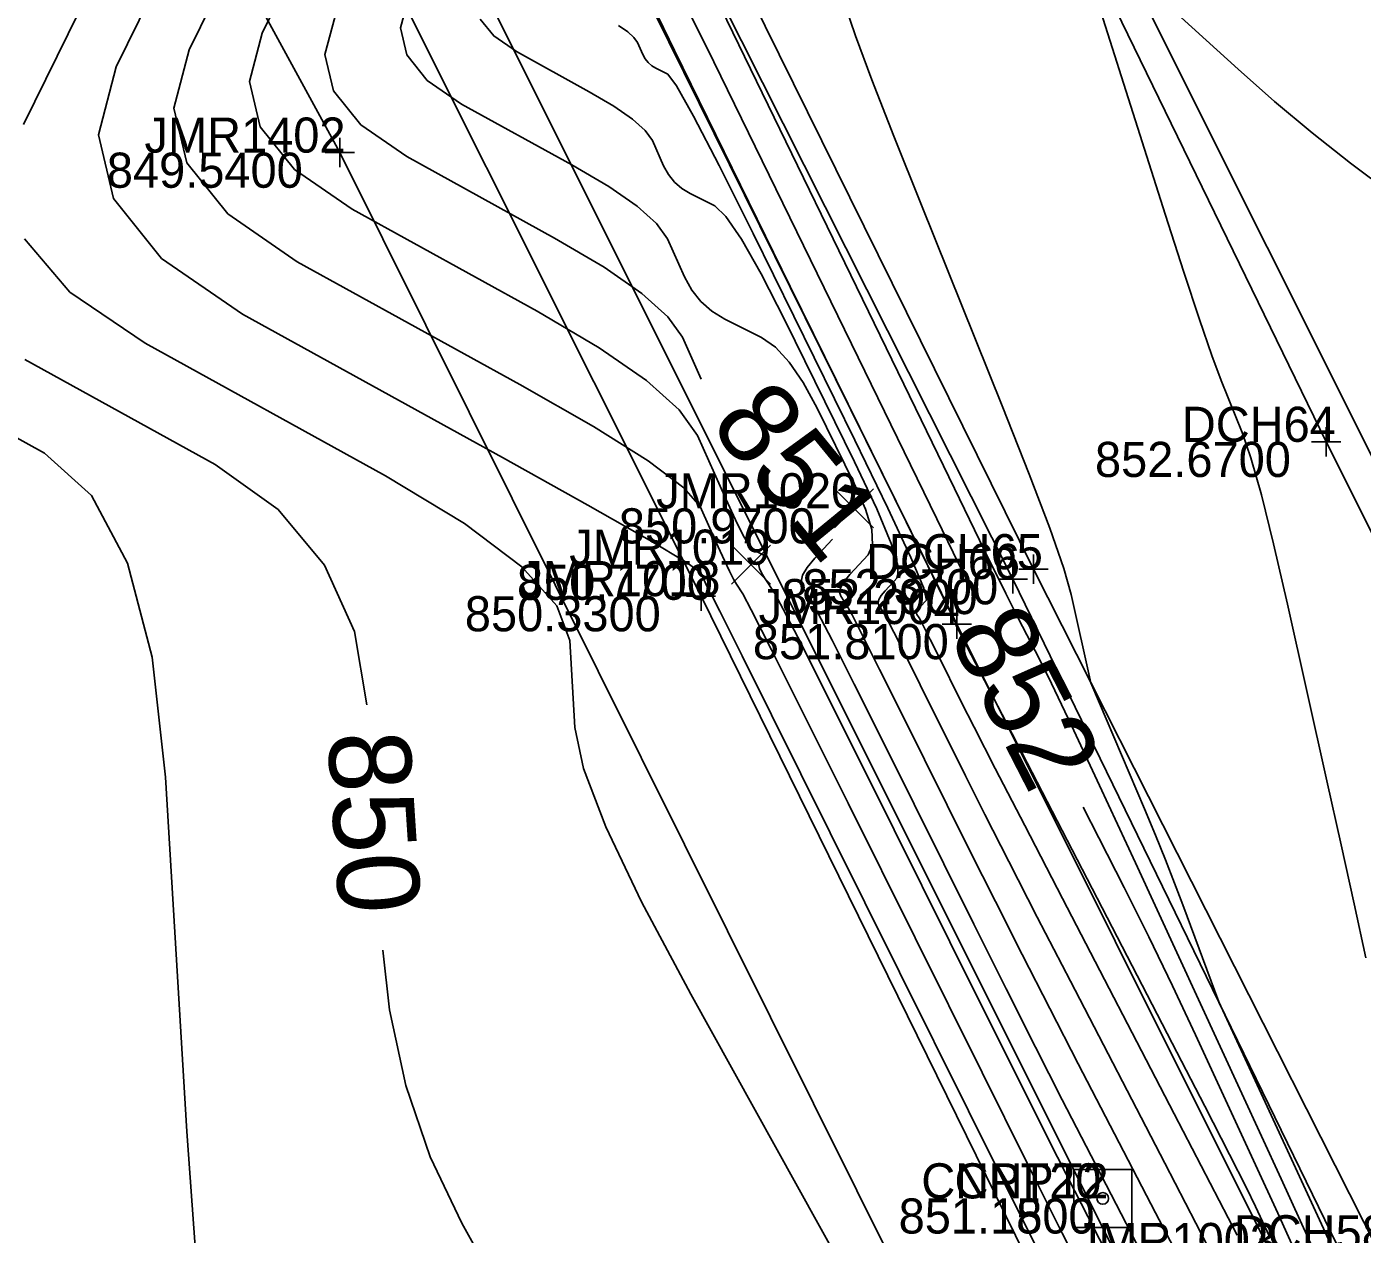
# Model space of a CAD drawing. Extents: x 1654928 to 1810050, y 486881 to 626330.
# Drawn here: x 1801345.62 to 1801391.24, y 489876.6 to 489917.85 of the extents above; entities that cross this region are included whole.
import ezdxf

# ---------------------------------------------------------------- set-up
doc = ezdxf.new("R2010")
doc.units = 0
for name, color, linetype in [('DT_X_Contour_Major', 7, 'Continuous'), ('DT_X_Contour_Minor', 7, 'Continuous'), ('PV_X_EOP', 7, 'Continuous'), ('PV_X_Shoulder', 7, 'Continuous'), ('RD_X_Fence', 7, 'Continuous'), ('RW_X_Esmt_SH', 7, 'Continuous'), ('SV_P_Control_Cells_Set', 7, 'Continuous'), ('SV_X_Break_Lines', 7, 'Continuous'), ('SV_X_Center_of_Pavt', 7, 'Continuous'), ('SV_X_CL_Survey_20', 7, 'Continuous'), ('SV_X_Control_Cells_Found', 7, 'Continuous'), ('SV_X_Occupation_Line', 7, 'Continuous'), ('SV_X_Random_Point', 7, 'Continuous'), ('SV_X_Shot_Marker', 7, 'Continuous'), ('SV_X_Text_Elevation', 7, 'Continuous'), ('SV_X_Text_Name', 7, 'Continuous')]:
    doc.layers.add(name, color=color, linetype=linetype)

msp = doc.modelspace()

# ---------------------------------------------------------------- linework, layer by layer
at = {"layer": 'DT_X_Contour_Major'}
for points in [[(1801344.553, 489964.664), (1801350.197, 489953.606), (1801351.808, 489950.439), (1801352.274, 489949.518), (1801354.342, 489945.414), (1801359.53, 489935.147), (1801360.682, 489932.876), (1801361.734, 489930.824), (1801362.685, 489928.991), (1801363.535, 489927.377), (1801365.669, 489923.365), (1801366.482, 489921.817), (1801367.323, 489920.181), (1801368.19, 489918.458), (1801369.084, 489916.647), (1801372.39, 489909.892), (1801374.021, 489906.547), (1801376.699, 489901.037), (1801377.442, 489899.52), (1801377.866, 489898.669)], [(1801356.15, 489918.213), (1801355.804, 489916.896), (1801356.096, 489915.656), (1801357.029, 489914.495), (1801358.601, 489913.412), (1801363.646, 489910.629), (1801365.338, 489909.635), (1801366.629, 489908.739), (1801367.521, 489907.942), (1801368.012, 489907.244), (1801368.654, 489905.814)], [(1801345.549, 489906.479), (1801352.05, 489902.893), (1801354.204, 489901.363), (1801355.79, 489899.462), (1801356.809, 489897.192), (1801357.237, 489894.691)], [(1801373.141, 489900.342), (1801372.537, 489899.696), (1801372.276, 489899.383), (1801372.12, 489899.114), (1801372.068, 489898.889), (1801372.12, 489898.708), (1801372.398, 489898.285), (1801372.633, 489897.858), (1801373.129, 489896.893), (1801373.886, 489895.391), (1801374.904, 489893.351), (1801377.967, 489887.196), (1801379.069, 489884.99), (1801380.076, 489882.991), (1801380.988, 489881.197), (1801381.806, 489879.609), (1801383.86, 489875.648)], [(1801381.698, 489891.194), (1801382.241, 489890.146), (1801383.105, 489888.454), (1801383.943, 489886.769), (1801384.753, 489885.091), (1801385.537, 489883.419), (1801387.592, 489878.971), (1801388.351, 489877.322), (1801389.084, 489875.712)], [(1801357.786, 489886.311), (1801358.009, 489884.27), (1801358.57, 489881.682), (1801359.394, 489879.254), (1801360.479, 489876.984), (1801363.724, 489871.142)]]:
    msp.add_lwpolyline(points, dxfattribs=at)
at = {"layer": 'DT_X_Contour_Minor'}
for points in [[(1801343.748, 489949.023), (1801345.654, 489944.672), (1801346.311, 489942.99), (1801346.853, 489941.21), (1801347.28, 489939.331), (1801347.592, 489937.353), (1801348.27, 489931.946), (1801348.519, 489930.099), (1801348.757, 489928.615), (1801348.984, 489927.493), (1801349.2, 489926.733), (1801349.76, 489925.189), (1801349.818, 489924.427), (1801349.574, 489923.3), (1801349.027, 489921.809), (1801348.177, 489919.952), (1801345.505, 489914.513)], [(1801351.803, 489922.842), (1801348.676, 489916.476), (1801348.066, 489914.157), (1801348.582, 489911.976), (1801350.222, 489909.933), (1801352.988, 489908.028), (1801361.865, 489903.132), (1801364.785, 489901.508), (1801366.887, 489900.31), (1801368.173, 489899.539), (1801368.641, 489899.192), (1801368.856, 489898.716), (1801368.901, 489898.621), (1801368.937, 489898.551), (1801368.963, 489898.505), (1801369.02, 489898.419), (1801369.289, 489897.888), (1801370.052, 489896.361), (1801373.062, 489890.318), (1801380.158, 489876.06)], [(1801353.845, 489922.505), (1801351.168, 489917.055), (1801350.645, 489915.07), (1801351.086, 489913.203), (1801352.491, 489911.454), (1801354.859, 489909.823), (1801362.458, 489905.631), (1801364.981, 489904.191), (1801366.848, 489903.016), (1801368.061, 489902.105), (1801368.619, 489901.458), (1801369.235, 489900.087), (1801369.447, 489899.622), (1801369.622, 489899.254), (1801369.76, 489898.983), (1801369.86, 489898.809), (1801370.08, 489898.476), (1801370.366, 489897.935), (1801371.061, 489896.564), (1801372.164, 489894.362), (1801373.676, 489891.329), (1801378.252, 489882.134), (1801379.795, 489879.037), (1801380.991, 489876.643), (1801381.841, 489874.952)], [(1801355.886, 489922.168), (1801353.659, 489917.634), (1801353.224, 489915.983), (1801353.591, 489914.43), (1801354.76, 489912.975), (1801356.73, 489911.618), (1801363.052, 489908.13), (1801365.172, 489906.884), (1801366.791, 489905.762), (1801367.908, 489904.763), (1801368.524, 489903.888), (1801369.497, 489901.719), (1801369.828, 489901.001), (1801370.093, 489900.475), (1801370.292, 489900.139), (1801370.424, 489899.994), (1801370.686, 489899.862), (1801370.766, 489899.812), (1801370.809, 489899.762), (1801370.816, 489899.711), (1801370.785, 489899.659), (1801370.655, 489899.52), (1801370.629, 489899.45), (1801370.647, 489899.343), (1801370.71, 489899.2), (1801370.818, 489899.02), (1801371.165, 489898.492), (1801371.458, 489897.96), (1801372.076, 489896.757), (1801373.02, 489894.883), (1801374.29, 489892.34), (1801378.11, 489884.665), (1801379.432, 489882.014), (1801380.534, 489879.817), (1801381.415, 489878.074), (1801382.075, 489876.786), (1801384.027, 489873.021)], [(1801392.192, 489912.176), (1801390.839, 489913.186), (1801389.522, 489914.225), (1801388.242, 489915.294), (1801386.998, 489916.394), (1801381.278, 489921.594), (1801384.501, 489911.447), (1801385.139, 489909.461), (1801385.672, 489907.852), (1801386.098, 489906.62), (1801386.42, 489905.765), (1801387.135, 489903.988), (1801387.433, 489903.122), (1801387.791, 489901.856), (1801388.207, 489900.191), (1801388.683, 489898.127), (1801390.03, 489892.09), (1801390.515, 489889.909), (1801390.958, 489887.895), (1801391.359, 489886.047)], [(1801369.129, 489918.901), (1801375.971, 489904.816), (1801377.305, 489902.073), (1801378.336, 489899.963), (1801379.063, 489898.487), (1801379.487, 489897.645), (1801380.213, 489896.242), (1801380.622, 489895.413), (1801381.304, 489893.977), (1801382.258, 489891.935), (1801383.485, 489889.287), (1801387.121, 489881.416), (1801388.462, 489878.499), (1801389.76, 489875.65)], [(1801358.642, 489918.793), (1801358.383, 489917.808), (1801358.601, 489916.883), (1801359.298, 489916.016), (1801360.472, 489915.207), (1801364.24, 489913.129), (1801365.503, 489912.386), (1801366.468, 489911.717), (1801367.133, 489911.122), (1801367.5, 489910.6), (1801368.08, 489909.308), (1801368.33, 489908.854), (1801368.643, 489908.462), (1801369.019, 489908.132), (1801369.459, 489907.864), (1801370.718, 489907.232), (1801371.191, 489906.904), (1801371.664, 489906.393), (1801372.139, 489905.701), (1801372.614, 489904.826), (1801373.884, 489902.25), (1801374.271, 489901.373), (1801374.48, 489900.675), (1801374.511, 489900.155), (1801374.364, 489899.813), (1801373.736, 489899.14), (1801373.539, 489898.905), (1801373.421, 489898.702), (1801373.382, 489898.533), (1801373.421, 489898.397), (1801373.631, 489898.078), (1801373.808, 489897.756), (1801374.181, 489897.03), (1801374.751, 489895.898), (1801375.518, 489894.362), (1801377.825, 489889.727), (1801378.706, 489887.967), (1801379.618, 489886.164), (1801380.562, 489884.319), (1801381.536, 489882.431), (1801384.178, 489877.338), (1801385.046, 489875.663)], [(1801366.999, 489918.559), (1801367.744, 489917.038), (1801371.691, 489908.974), (1801375.651, 489900.938), (1801376.394, 489899.43), (1801376.923, 489898.353), (1801377.238, 489897.704), (1801377.341, 489897.485), (1801377.331, 489897.474), (1801377.328, 489897.47), (1801377.326, 489897.467), (1801377.325, 489897.464), (1801377.326, 489897.462), (1801377.329, 489897.457), (1801377.332, 489897.452), (1801377.338, 489897.44), (1801377.347, 489897.421), (1801377.36, 489897.396), (1801377.398, 489897.32), (1801377.439, 489897.24), (1801377.532, 489897.059), (1801377.679, 489896.775), (1801377.879, 489896.39), (1801378.936, 489894.353), (1801384.745, 489883.131), (1801385.856, 489880.979), (1801386.701, 489879.332), (1801387.279, 489878.19), (1801387.59, 489877.552), (1801388.064, 489876.525)], [(1801373.559, 489918.61), (1801373.927, 489917.536), (1801374.487, 489916.035), (1801375.236, 489914.106), (1801376.176, 489911.749), (1801378.937, 489904.895), (1801379.861, 489902.566), (1801380.562, 489900.717), (1801381.04, 489899.348), (1801381.296, 489898.461), (1801381.97, 489895.442), (1801383.798, 489891.132), (1801384.173, 489890.234), (1801384.517, 489889.39), (1801384.828, 489888.599), (1801385.107, 489887.861), (1801386.335, 489884.541), (1801389.294, 489878.136), (1801389.908, 489876.801), (1801390.484, 489875.538)], [(1801361.106, 489918.109), (1801361.567, 489917.536), (1801362.343, 489917.002), (1801364.833, 489915.628), (1801365.668, 489915.137), (1801366.306, 489914.695), (1801366.746, 489914.301), (1801366.989, 489913.957), (1801367.372, 489913.102), (1801367.537, 489912.802), (1801367.744, 489912.543), (1801367.993, 489912.325), (1801368.284, 489912.148), (1801369.116, 489911.73), (1801369.5, 489911.367), (1801370.029, 489910.592), (1801370.702, 489909.404), (1801371.52, 489907.805), (1801373.893, 489902.988), (1801374.652, 489901.387), (1801375.149, 489900.195), (1801375.384, 489899.411), (1801375.357, 489899.037), (1801374.934, 489898.585), (1801374.802, 489898.427), (1801374.723, 489898.291), (1801374.696, 489898.177), (1801374.723, 489898.085), (1801374.863, 489897.871), (1801374.982, 489897.655), (1801375.233, 489897.166), (1801375.617, 489896.406), (1801376.132, 489895.374), (1801377.683, 489892.258), (1801378.343, 489890.944), (1801379.16, 489889.338), (1801380.135, 489887.441), (1801381.267, 489885.253), (1801384.496, 489879.029), (1801385.556, 489876.984), (1801386.774, 489874.627)], [(1801365.834, 489917.888), (1801366.145, 489917.672), (1801366.359, 489917.481), (1801366.477, 489917.313), (1801366.664, 489916.897), (1801366.744, 489916.751), (1801366.845, 489916.624), (1801366.966, 489916.518), (1801367.108, 489916.432), (1801367.513, 489916.228), (1801367.809, 489915.831), (1801368.393, 489914.791), (1801369.265, 489913.108), (1801370.426, 489910.783), (1801373.903, 489903.727), (1801375.034, 489901.401), (1801375.819, 489899.715), (1801376.257, 489898.668), (1801376.349, 489898.261), (1801376.132, 489898.03), (1801376.065, 489897.949), (1801376.024, 489897.879), (1801376.011, 489897.821), (1801376.024, 489897.774), (1801376.096, 489897.664), (1801376.157, 489897.553), (1801376.286, 489897.303), (1801376.482, 489896.914), (1801376.746, 489896.385), (1801377.54, 489894.789), (1801377.98, 489893.92), (1801378.702, 489892.512), (1801379.708, 489890.564), (1801380.998, 489888.075), (1801384.813, 489880.719), (1801386.961, 489876.577)], [(1801345.543, 489910.605), (1801347.091, 489908.778), (1801349.661, 489907.037), (1801357.872, 489902.507), (1801360.575, 489900.882), (1801362.524, 489899.403), (1801363.72, 489898.07), (1801364.163, 489896.883), (1801364.34, 489893.915), (1801364.637, 489892.511), (1801365.395, 489890.524), (1801366.615, 489887.955), (1801368.296, 489884.804), (1801373.394, 489875.625)], [(1801341.437, 489905.92), (1801346.227, 489903.278), (1801347.832, 489901.843), (1801349.056, 489899.522), (1801349.899, 489896.314), (1801350.36, 489892.219), (1801351.08, 489880.117), (1801351.381, 489876.029)]]:
    msp.add_lwpolyline(points, dxfattribs=at)
at = {"layer": 'PV_X_EOP'}
msp.add_lwpolyline([(1801513.785, 489634.043), (1801503.26, 489654.965), (1801492.692, 489675.84), (1801481.803, 489697.704), (1801472.078, 489717.629), (1801460.782, 489739.414), (1801448.005, 489764.97), (1801436.553, 489786.89), (1801425.237, 489809.697), (1801414.345, 489830.894), (1801402.21, 489854.742), (1801391.781, 489876.056), (1801380.008, 489899.32), (1801369.395, 489920.807), (1801356.62, 489946.308), (1801346.845, 489965.404), (1801335.257, 489988.444)], dxfattribs=at)
at = {"layer": 'PV_X_Shoulder'}
msp.add_lwpolyline([(1801513.053, 489633.484), (1801502.425, 489654.401), (1801492.155, 489675.438), (1801481.048, 489697.245), (1801471.095, 489717.056), (1801459.974, 489738.844), (1801446.996, 489764.517), (1801435.938, 489786.184), (1801424.33, 489809.156), (1801413.386, 489830.353), (1801401.606, 489854.259), (1801390.811, 489875.349), (1801379.301, 489898.985), (1801368.607, 489920.204), (1801355.561, 489945.921), (1801346.174, 489964.922), (1801334.144, 489988.199)], dxfattribs=at)
at = {"layer": 'RD_X_Fence'}
msp.add_lwpolyline([(1801327.157, 489980.825), (1801341.337, 489952.815), (1801353.978, 489927.719), (1801368.649, 489898.399), (1801382.749, 489869.731), (1801399.284, 489836.538), (1801405.615, 489823.327), (1801393.757, 489823.044), (1801375.98, 489823.449), (1801361.092, 489823.97), (1801335.059, 489824.221), (1801306.244, 489824.992)], dxfattribs=at)
at = {"layer": 'RW_X_Esmt_SH'}
msp.add_line((1801533.563, 489574.54), (1801308.538, 490024.454), dxfattribs=at)
at = {"layer": 'SV_P_Control_Cells_Set'}
msp.add_lwpolyline([(1801381.382, 489878.82), (1801383.362, 489878.82), (1801383.362, 489876.839), (1801381.382, 489876.839), (1801381.382, 489878.82)], dxfattribs=at)
msp.add_circle((1801382.372, 489877.829), 0.2, dxfattribs=at)
at = {"layer": 'SV_X_Break_Lines'}
msp.add_lwpolyline([(1801419.479, 489816.264), (1801413.606, 489827.582), (1801399.229, 489854.903), (1801388.205, 489875.792), (1801377.391, 489897.446), (1801365.991, 489920.501), (1801353.319, 489946.375), (1801342.526, 489967.898), (1801332.595, 489987.823)], dxfattribs=at)
at = {"layer": 'SV_X_Center_of_Pavt'}
msp.add_lwpolyline([(1801523.585, 489638.313), (1801512.853, 489659.481), (1801502.374, 489680.412), (1801490.819, 489703.952), (1801481.428, 489721.68), (1801470.803, 489742.834), (1801457.335, 489769.613), (1801446.389, 489792.464), (1801435.307, 489813.792), (1801423.54, 489836.522), (1801412.234, 489859.298), (1801401.202, 489881.345), (1801390.005, 489903.67), (1801378.784, 489926.715), (1801366.669, 489950.371), (1801356.567, 489970.63), (1801345.517, 489992.708)], dxfattribs=at)
at = {"layer": 'SV_X_CL_Survey_20'}
msp.add_line((1802886.975, 486913.246), (1801128.538, 490429.055), dxfattribs=at)
msp.add_line((1802886.975, 486913.246), (1801128.538, 490429.055), dxfattribs=at)
at = {"layer": 'SV_X_Control_Cells_Found'}
msp.add_lwpolyline([(1801381.382, 489878.821), (1801383.362, 489878.821), (1801383.362, 489876.839), (1801381.382, 489876.839), (1801381.382, 489878.821)], dxfattribs=at)
msp.add_circle((1801382.372, 489877.829), 0.2, dxfattribs=at)
at = {"layer": 'SV_X_Occupation_Line'}
msp.add_lwpolyline([(1801323.637, 489975.339), (1801342.746, 489938.404), (1801356.309, 489913.548), (1801376.911, 489872.203), (1801387.619, 489838.687), (1801379.855, 489831.976), (1801347.713, 489831.536), (1801304.639, 489830.454)], dxfattribs=at)
at = {"layer": 'SV_X_Random_Point'}
for p, q in [((1801373.206, 489900.733), (1801374.539, 489902.068)), ((1801373.206, 489902.068), (1801374.539, 489900.733)), ((1801369.688, 489898.807), (1801371.022, 489900.142)), ((1801369.688, 489900.142), (1801371.022, 489898.807))]:
    msp.add_line(p, q, dxfattribs=at)
at = {"layer": 'SV_X_Shot_Marker'}
for p, q in [((1801356.309, 489914.048), (1801356.309, 489913.048)), ((1801355.809, 489913.548), (1801356.809, 489913.548)), ((1801356.309, 489913.548), (1801356.309, 489913.548)), ((1801390.005, 489904.17), (1801390.005, 489903.17)), ((1801389.505, 489903.67), (1801390.505, 489903.67)), ((1801390.005, 489903.67), (1801390.005, 489903.67)), ((1801380.008, 489899.82), (1801380.008, 489898.82)), ((1801379.301, 489899.485), (1801379.301, 489898.485)), ((1801379.508, 489899.32), (1801380.508, 489899.32)), ((1801380.008, 489899.32), (1801380.008, 489899.32)), ((1801368.649, 489898.899), (1801368.649, 489897.899)), ((1801378.801, 489898.985), (1801379.801, 489898.985)), ((1801379.301, 489898.985), (1801379.301, 489898.985)), ((1801368.149, 489898.399), (1801369.149, 489898.399)), ((1801368.649, 489898.399), (1801368.649, 489898.399)), ((1801377.391, 489897.946), (1801377.391, 489896.946)), ((1801376.891, 489897.446), (1801377.891, 489897.446)), ((1801377.391, 489897.446), (1801377.391, 489897.446))]:
    msp.add_line(p, q, dxfattribs=at)

# ---------------------------------------------------------------- texts
at = {"layer": 'DT_X_Contour_Major'}
for s, rotation, p in [('851', 309.3553, (1801368.89, 489904.235)), ('852', 297.1417, (1801377.074, 489897.111)), ('850', 273.7488, (1801355.889, 489893.709))]:
    msp.add_text(s, height=2.8, rotation=rotation, dxfattribs=at).set_placement(p)
at = {"layer": 'SV_X_Text_Elevation'}
for s, p in [('849.5400', (1801348.353, 489912.348)), ('852.6700', (1801382.106, 489902.47)), ('850.9700', (1801365.842, 489900.2)), ('850.7700', (1801362.362, 489898.274)), ('852.3700', (1801372.109, 489898.12)), ('852.2900', (1801371.402, 489897.785)), ('850.3300', (1801360.581, 489897.199)), ('851.8100', (1801370.419, 489896.247)), ('851.1800', (1801375.4, 489876.629)), ('851.1500', (1801375.4, 489876.629))]:
    msp.add_text(s, height=1.2, dxfattribs=at).set_placement(p)
at = {"layer": 'SV_X_Text_Name'}
for s, p in [('JMR1402', (1801349.639, 489913.548)), ('DCH64', (1801385.073, 489903.67)), ('JMR1020', (1801367.118, 489901.4)), ('JMR1019', (1801364.149, 489899.474)), ('DCH66', (1801374.284, 489898.985)), ('DCH65', (1801375.066, 489899.32)), ('JMR1018', (1801362.443, 489898.399)), ('JMR1004', (1801370.617, 489897.446)), ('CNPT20', (1801376.174, 489877.829)), ('CNPT2', (1801377.308, 489877.829)), ('JMR1003', (1801381.422, 489875.792)), ('DCH58', (1801386.85, 489876.056))]:
    msp.add_text(s, height=1.2, dxfattribs=at).set_placement(p)

doc.saveas('drawing.dxf')
